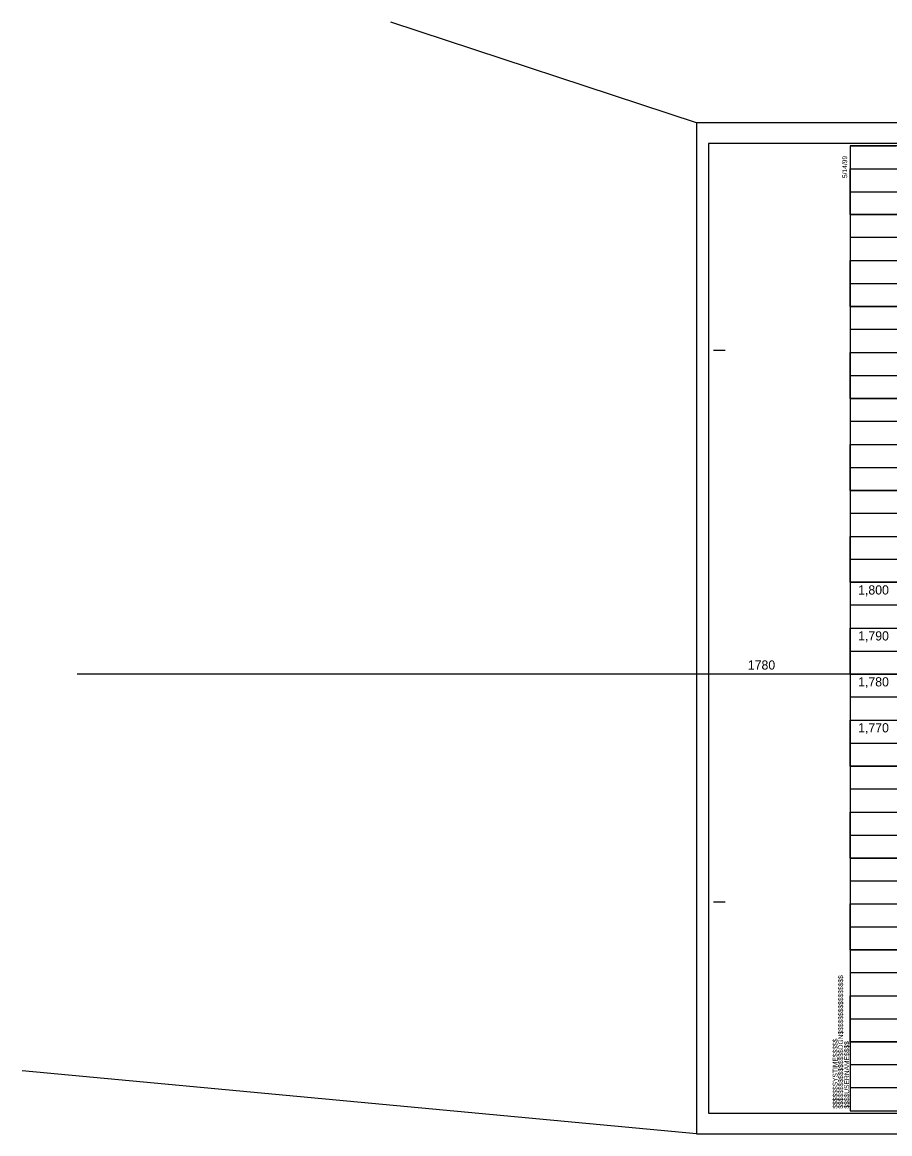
# Model space of a CAD drawing. Extents: x 572269 to 579912, y -56875 to -49627.
# Drawn here: x 572934 to 573878, y -53848 to -52638 of the extents above; entities that cross this region are included whole.
import ezdxf

# ---------------------------------------------------------------- set-up
doc = ezdxf.new("R2010")
doc.units = 0
for name, color, linetype in [('Exist Vertical Profile Vertical Axis Label', 7, 'Continuous'), ('Scratch_Level_3', 7, 'Continuous'), ('Scratch_Level_6', 7, 'Continuous'), ('Sheet Cutting Line CELL', 7, 'Continuous'), ('Sheet DOT Grid CELL', 7, 'Continuous'), ('Sheet Plot Border Inside CELL', 7, 'Continuous'), ('Sheet Plot Border Outside CELL', 7, 'Continuous'), ('Sheet Profile CELL', 7, 'Continuous'), ('Sheet Profile Grid Major CELL', 7, 'Continuous'), ('Sheet Profile Grid Middle CELL', 7, 'Continuous'), ('Sheet Profile Grid Minor CELL', 7, 'Continuous')]:
    doc.layers.add(name, color=color, linetype=linetype)

# ---------------------------------------------------------------- blocks, each defined once
blk = doc.blocks.new('PROFILE SHEET SINGLE')
at = {"layer": 'Sheet Cutting Line CELL'}
for p, q in [((30.34, 21.5), (-3.34, 21.5)), ((-3.34, 21.5), (-3.34, -0.5)), ((-3.34, -0.5), (30.34, -0.5))]:
    blk.add_line(p, q, dxfattribs=at)
at = {"layer": 'Sheet DOT Grid CELL'}
for p, q in [((0, 20.5), (25.999, 20.5)), ((0, 19.5), (25.999, 19.5)), ((0, 18.5), (25.999, 18.5)), ((0, 17.5), (30, 17.5)), ((0, 16.5), (30, 16.5)), ((0, 15.5), (30, 15.5)), ((0, 14.5), (30, 14.5)), ((0, 13.5), (30, 13.5)), ((0, 12.5), (30, 12.5)), ((0, 11.5), (30, 11.5)), ((0, 10.5), (30, 10.5)), ((0, 9.5), (30, 9.5)), ((0, 8.5), (30, 8.5)), ((0, 7.5), (30, 7.5)), ((0, 6.5), (30, 6.5)), ((0, 5.5), (30, 5.5)), ((0, 4.5), (30, 4.5)), ((0, 3.5), (30, 3.5)), ((0, 2.5), (30, 2.5)), ((0, 1.5), (30, 1.5))]:
    blk.add_line(p, q, dxfattribs=at)
at = {"layer": 'Sheet Plot Border Inside CELL'}
blk.add_lwpolyline([(30.25, 21.051), (-3.08, 21.051), (-3.08, -0.051), (30.25, -0.051)], close=True, dxfattribs=at)
at = {"layer": 'Sheet Plot Border Outside CELL'}
blk.add_lwpolyline([(30.34, 21.5), (-3.34, 21.5), (-3.34, -0.5), (30.34, -0.5)], close=True, dxfattribs=at)
at = {"layer": 'Sheet Profile CELL'}
for p, q in [((-2.97, 16.55), (-2.72, 16.55)), ((-2.97, 4.55), (-2.72, 4.55)), ((30, 0.5), (0, 0.5)), ((0, 0), (0, 0)), ((0, 0), (0, 0)), ((0, 0), (0, 0)), ((0, 0), (0, 0)), ((0, 0), (0, 0)), ((0, 0), (0, 0))]:
    blk.add_line(p, q, dxfattribs=at)
blk.add_lwpolyline([(30, 21), (0, 21), (0, 0), (30, 0)], close=True, dxfattribs=at)
blk.add_lwpolyline([(0.75, 0), (0.75, 0)], dxfattribs=at)
at = {"layer": 'Sheet Profile Grid Major CELL'}
for points in [[(0, 21), (1, 21)], [(25.999, 19.5), (0.002, 19.5), (0.002, 20.499), (25.999, 20.499)], [(30, 17.5), (0, 17.5), (0, 18.5), (25.999, 18.5)], [(30, 15.5), (0, 15.5), (0, 16.5), (30, 16.5)], [(30, 13.5), (0, 13.5), (0, 14.5), (30, 14.5)], [(30, 11.5), (0, 11.5), (0, 12.5), (30, 12.5)], [(30, 9.5), (0, 9.5), (0, 10.5), (30, 10.5)], [(30, 7.5), (0, 7.5), (0, 8.5), (30, 8.5)], [(30, 5.5), (0, 5.5), (0, 6.5), (30, 6.5)], [(30, 3.5), (0, 3.5), (0, 4.5), (30, 4.5)], [(30, 1.5), (0, 1.5), (0, 2.5), (30, 2.5)]]:
    blk.add_lwpolyline(points, dxfattribs=at)
at = {"layer": 'Sheet Profile Grid Middle CELL'}
for points in [[(0, 20), (25.999, 20)], [(25.999, 19), (0, 19), (0, 17.999), (30, 17.999)], [(30, 17), (0, 17), (0, 16), (30, 16)], [(30, 15), (0, 15), (0, 14), (30, 14)], [(30, 13), (0, 13), (0, 12), (30, 12)], [(30, 11), (0, 11), (0, 10), (30, 10)], [(30, 9), (0, 9), (0, 8), (30, 8)], [(30, 7), (0, 7), (0, 6), (30, 6)], [(30, 5), (0, 5), (0, 4), (30, 4)], [(30, 3), (0, 3), (0, 2), (30, 2)], [(30, 1), (0, 1)]]:
    blk.add_lwpolyline(points, dxfattribs=at)
at = {"layer": 'Sheet Profile Grid Minor CELL'}
blk.add_lwpolyline([(1.039, 21), (0.2, 21), (0.3, 21), (0.4, 21), (0.6, 21), (0.7, 21), (0.8, 21), (0.9, 21)], dxfattribs=at)
at = {"layer": 'Sheet Profile CELL'}
for s, p in [('5/14/99', (-0.065, 20.296)), ('$$$$$$$$$$$$$$$$DGN$$$$$$$$$$$$$$$$', (-0.153, 0.047)), ('$$$$$$SYSTIME$$$$$', (-0.274, 0.047)), ('$$$$USERNAME$$$$', (-0.022, 0.048))]:
    blk.add_text(s, height=0.105, rotation=90, dxfattribs=at).set_placement(p)

msp = doc.modelspace()

# ---------------------------------------------------------------- linework, layer by layer
at = {"layer": 'Scratch_Level_3'}
for p, q in [((573667.7, -52747.7), (573335.1, -52638.3)), ((573667.7, -53847.7), (572934.1, -53779.1))]:
    msp.add_line(p, q, dxfattribs=at)
at = {"layer": 'Scratch_Level_6'}
msp.add_line((576826.8, -53347.7), (572993.9, -53347.7), dxfattribs=at)

# ---------------------------------------------------------------- block references
at = {"layer": 'Sheet Cutting Line CELL', "xscale": 50, "yscale": 50}
msp.add_blockref('PROFILE SHEET SINGLE', (573834.7, -53822.7), dxfattribs=at)

# ---------------------------------------------------------------- texts
at = {"layer": 'Exist Vertical Profile Vertical Axis Label'}
for s, p in [('1,800', (573843.4, -53261)), ('1,790', (573843.4, -53311)), ('1,780', (573843.4, -53361)), ('1,770', (573843.4, -53411))]:
    msp.add_text(s, height=10, dxfattribs=at).set_placement(p)
at = {"layer": 'Scratch_Level_6'}
msp.add_text('1780', height=10, dxfattribs=at).set_placement((573723.4, -53342.7))

doc.saveas('drawing.dxf')
